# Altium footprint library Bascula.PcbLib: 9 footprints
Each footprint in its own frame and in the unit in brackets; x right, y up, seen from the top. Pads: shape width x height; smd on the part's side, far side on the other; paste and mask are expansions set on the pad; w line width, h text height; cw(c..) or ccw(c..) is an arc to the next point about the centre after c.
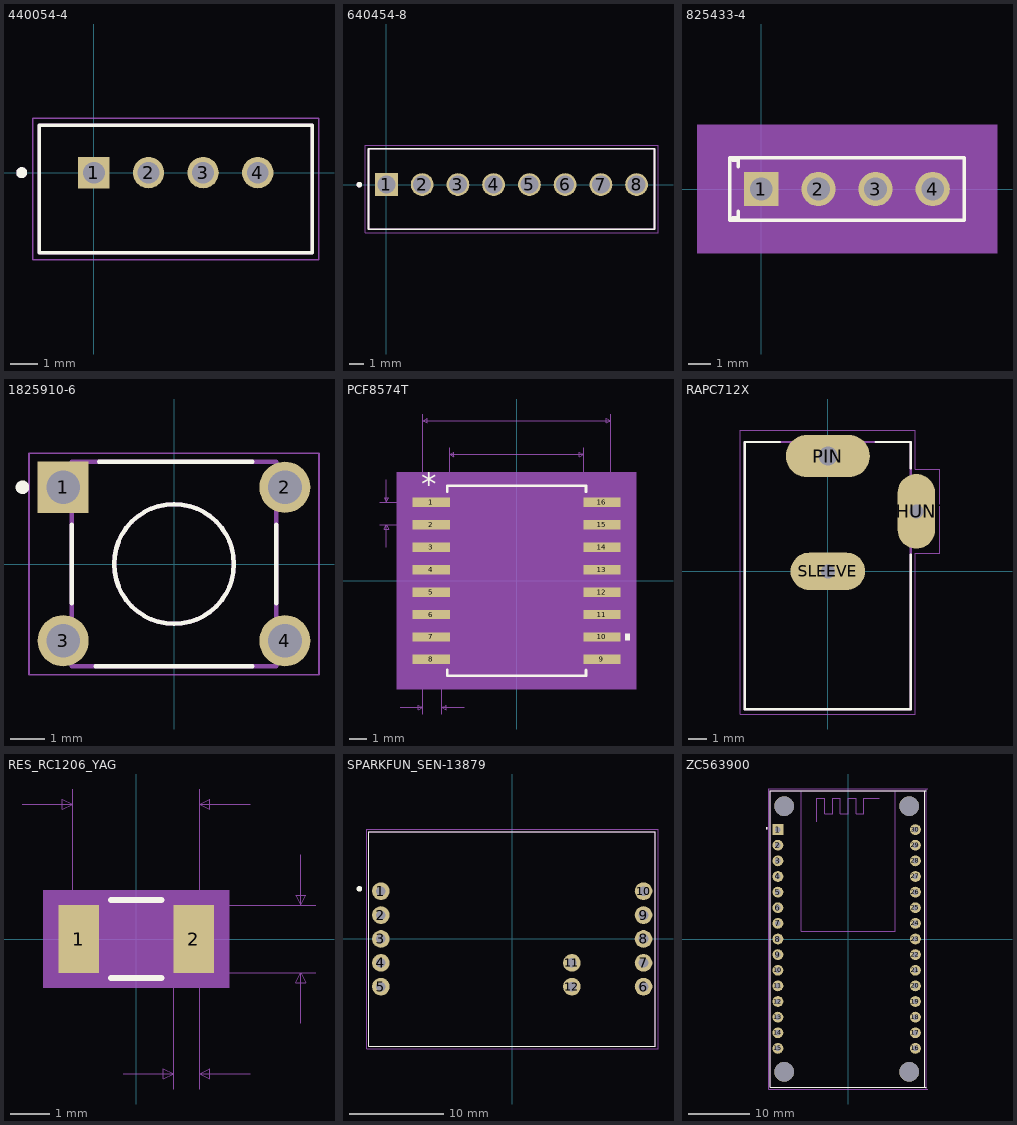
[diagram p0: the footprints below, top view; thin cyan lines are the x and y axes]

## 440054-4 [mm] "4 pin male connector for PCB"
pads (4):
  rect 1.15x1.15 hole 0.8: 1(0,0)
  round 1.15 hole 0.8: 2(2.007,0) 3(4.013,0) 4(6.02,0)
Top Overlay:
  circle w0.2: c-2.65,0 r0.1
  lines w0.127: -2,-2.95 8.02,-2.95 8.02,1.75 -2,1.75 -2,-2.95
Mechanical 13:
  circle w0.2: c-2.65,0 r0.1
  lines w0.127: -2,-2.95 8.02,-2.95 ; -2,-2.95 8.02,-2.95 ; -2,-2.95 -2,1.75 8.02,1.75 8.02,-2.95
Mechanical 15:
  lines w0.05: -2.25,-3.2 8.27,-3.2 8.27,2 -2.25,2 -2.25,-3.2
3D body "440054-4.stp": height 6.06, standoff -3.39, extent -1.977,-2.973 8.023,1.727

## 640454-8 [mm] "8 pin male header connector 2.54MM"
pads (8):
  rect 1.62x1.62 hole 1.27: 1(0,0)
  round 1.62 hole 1.27: 2(2.54,0) 3(5.08,0) 4(7.62,0) 5(10.16,0) 6(12.7,0) 7(15.24,0) 8(17.78,0)
Top Overlay:
  circle w0.2: c-1.92,0 r0.1
  lines w0.127: -1.27,-3.17 -1.27,2.55 19.05,2.55 19.05,-3.17 -1.27,-3.17
Mechanical 13:
  circle w0.2: c-1.92,0 r0.1
  lines w0.127: -1.27,-3.17 -1.27,2.55 19.05,2.55 19.05,-3.17 ; -1.27,-3.17 19.05,-3.17 ; -1.27,-3.17 19.05,-3.17
Mechanical 15:
  lines w0.05: -1.52,-3.42 -1.52,2.8 19.3,2.8 19.3,-3.42 -1.52,-3.42
3D body "640454-8.stp": height 10.09, standoff -3.5, extent -1.245,-3.129 19.075,2.591

## 825433-4 [mil] "HDR_1X4_0.100\""
pads (4):
  rect 60x60 hole 40 mask+0: 1(0,0)
  round 60 hole 40 mask+0: 2(100,0) 3(200,0) 4(300,0)
Top Overlay:
  lines w6: -50,-50 -40,-50 -40,-38.46 ; -50,50 -40,50 -40,38.46 ; -55,-55 355,-55 355,55 -55,55 -55,-55
Mechanical 5:
  region: 412.5,-112.5 -112.5,-112.5 -112.5,112.5 412.5,112.5
Mechanical 7:
  lines w1: 0,-110 0,-40 ; 50,-100 0,-100 ; 250,-100 300,-100 ; 300,-110 300,-40 ; 0,-100 10,-105 10,-95 0,-100 ; 300,-100 290,-105 290,-95 300,-100 ; 400,0 395,-10 405,-10 400,0 ; 400,0 395,10 405,10 400,0 ; 340,0 410,0 340,0
  text "Default Padstyle: OX60Y60D40P" at -212.5,-250 h50
  text "Pin 1 Padstyle: SX60Y60D40P" at -187.5,-350 h50
  text "Alt 1 Padstyle: OX60Y90D30P" at -187.5,-450 h50
  text "Alt 2 Padstyle: OX90Y60D30P" at -187.5,-550 h50
  text ".3in/7.62mm (4 @ .1in/3mm)" at -12.5,-125 h25
Mechanical 13:
  lines w1: -50,-50 -40,-50 -40,50 -50,50 ; -50,-50 350,-50 350,50 -50,50 ; -50,-50 -50,50
Mechanical 15:
  region: 360,60 -60,60 -60,-60 360,-60
  lines w6: -60,-60 -60,60 360,60 360,-60 -60,-60
3D body "825433-4.stp": height 374.52, standoff -125.48, extent -47,-94.7 353,49
3D body: height 10, standoff 0, extent 0,0 10,10

## 1825910-6 [mm] "NO Button"
pads (4):
  rect 1.498x1.498 hole 0.99: 1(-3.25,2.25)
  round 1.498 hole 0.99: 2(3.25,2.25) 3(-3.25,-2.25) 4(3.25,-2.25)
Top Overlay:
  circle w0.2: c-4.445,2.25 r0.1
  circle w0.127: c0,0 r1.755
  lines w0.127: -2.995,-1.15 -2.995,1.15 ; -2.3,-2.995 2.3,-2.995 ; -2.2,2.995 2.3,2.995 ; 3,-1.15 3,1.15
Mechanical 13:
  circle w0.127: c0,0 r1.755
  lines w0.127: -2.995,-2.995 2.995,-2.995 2.995,2.995 -2.995,2.995 -2.995,-2.995
Mechanical 15:
  lines w0.05: -4.25,-3.25 4.25,-3.25 4.25,3.25 -4.25,3.25 -4.25,-3.25
3D body "1825910-6.STEP": height 5.01, standoff -3.51, extent -3.847,-2.944 3.951,3.046

## PCF8574T [mil] "IC Expansor ES"
pads (16):
  rect 83x21 smd paste+0 mask+0: 1(-190,175) 2(-190,125) 3(-190,75) 4(-190,25) 5(-190,-25) 6(-190,-75) 7(-190,-125) 8(-190,-175) 9(190,-175) 10(190,-125) 11(190,-75) 12(190,-25) 13(190,25) 14(190,75) 15(190,125) 16(190,175)
Top Overlay:
  region: 241.5,-117.5 251.5,-117.5 251.5,-132.5 241.5,-132.5
  lines w6: -154.5,-198.6 -154.5,-211.5 154.5,-211.5 154.5,-198.6 ; -154.5,198.6 -154.5,211.5 154.5,211.5 154.5,198.6
  text "*" at -212.5,191 h50
Mechanical 5:
  region: 266.5,-241.5 -266.5,-241.5 -266.5,241.5 266.5,241.5
Mechanical 7:
  lines w1: -305,125 -190,125 ; -305,175 -190,175 ; -290,75 -290,125 ; -290,225 -290,175 ; -259.5,-281.5 -209.5,-281.5 ; -209.5,-296.5 -209.5,0 -209.5,371.5 ; -166.5,-296.5 -166.5,0 ; -149.5,0 -149.5,296.5 ; -116.5,-281.5 -166.5,-281.5 ; 0,-206.5 264.5,-206.5 ; 0,206.5 264.5,206.5 ; 149.5,0 149.5,296.5 ; 209.5,0 209.5,371.5 ; -290,125 -295,115 -285,115 -290,125 ; -290,175 -295,185 -285,185 -290,175 ; -209.5,-281.5 -219.5,-276.5 -219.5,-286.5 -209.5,-281.5 ; -209.5,356.5 209.5,356.5 ; -209.5,356.5 -199.5,361.5 -199.5,351.5 -209.5,356.5 ; -166.5,-281.5 -156.5,-276.5 -156.5,-286.5 -166.5,-281.5 ; -149.5,281.5 149.5,281.5 ; -149.5,281.5 -139.5,286.5 -139.5,276.5 -149.5,281.5 ; 149.5,281.5 139.5,286.5 139.5,276.5 149.5,281.5 ; 209.5,356.5 199.5,361.5 199.5,351.5 209.5,356.5 ; 249.5,-206.5 249.5,206.5 ; 249.5,-206.5 244.5,-196.5 254.5,-196.5 249.5,-206.5 ; 249.5,206.5 244.5,196.5 254.5,196.5 249.5,206.5
  text "Default Padstyle: RX83Y21D0T" at -350,-406.5 h50
  text "Pin One Padstyle: RX83Y21D0T" at -350,-466.5 h50
  text "Alt 1 Padstyle: OX60Y90D30P" at -337.5,-646.5 h50
  text "Alt 2 Padstyle: OX90Y60D30P" at -337.5,-706.5 h50
  text "0.299in/7.595mm" at -93.75,301.5 h25
  text "0.419in/10.643mm" at -100,376.5 h25
  text "0.413in/10.49mm" at 269.5,-12.5 h25
  text "0.05in/1.27mm" at -472.5,137.5 h25
  text "0.043in/1.092mm" at -281.75,-326.5 h25
Mechanical 13:
  lines w0: -12,206.5 ccw(c0,206.5) 12,206.5
  lines w1: -209.5,-184.5 -209.5,-165.5 -149.5,-165.5 -149.5,-184.5 -209.5,-184.5 ; -209.5,-134.5 -209.5,-115.5 -149.5,-115.5 -149.5,-134.5 -209.5,-134.5 ; -209.5,-84.5 -209.5,-65.5 -149.5,-65.5 -149.5,-84.5 -209.5,-84.5 ; -209.5,-34.5 -209.5,-15.5 -149.5,-15.5 -149.5,-34.5 -209.5,-34.5 ; -209.5,15.5 -209.5,34.5 -149.5,34.5 -149.5,15.5 -209.5,15.5 ; -209.5,65.5 -209.5,84.5 -149.5,84.5 -149.5,65.5 -209.5,65.5 ; -209.5,115.5 -209.5,134.5 -149.5,134.5 -149.5,115.5 -209.5,115.5 ; -209.5,165.5 -209.5,184.5 -149.5,184.5 -149.5,165.5 -209.5,165.5 ; -149.5,-206.5 149.5,-206.5 149.5,206.5 -149.5,206.5 -149.5,-206.5 ; 149.5,-184.5 149.5,-165.5 209.5,-165.5 209.5,-184.5 149.5,-184.5 ; 149.5,-134.5 149.5,-115.5 209.5,-115.5 209.5,-134.5 149.5,-134.5 ; 149.5,-84.5 149.5,-65.5 209.5,-65.5 209.5,-84.5 149.5,-84.5 ; 149.5,-34.5 149.5,-15.5 209.5,-15.5 209.5,-34.5 149.5,-34.5 ; 149.5,15.5 149.5,34.5 209.5,34.5 209.5,15.5 149.5,15.5 ; 149.5,65.5 149.5,84.5 209.5,84.5 209.5,65.5 149.5,65.5 ; 149.5,115.5 149.5,134.5 209.5,134.5 209.5,115.5 149.5,115.5 ; 149.5,165.5 149.5,184.5 209.5,184.5 209.5,165.5 149.5,165.5
  text "*" at -147,153.5 h50
Mechanical 15:
  region: -169.5,-205.5 -251.5,-205.5 -251.5,205.5 -169.5,205.5 -169.5,226.5 169.5,226.5 169.5,205.5 251.5,205.5 251.5,-205.5 169.5,-205.5 169.5,-226.5 -169.5,-226.5
  lines w6: -251.5,-205.5 -251.5,205.5 -169.5,205.5 -169.5,226.5 169.5,226.5 169.5,205.5 251.5,205.5 251.5,-205.5 169.5,-205.5 169.5,-226.5 -169.5,-226.5 -169.5,-205.5 -251.5,-205.5
3D body "SOT162-1_NXP.step": height 104.09, standoff 0, extent -208.98,-207 210,205.99
3D body: height 10, standoff 0, extent 0,0 10,10

## RAPC712X [mm] "Power Jack Barrel TH"
pads (3):
  oval 4.56x2.28 hole 1.02 square: PIN(0,6.25)
  oval 2.025x4.05 hole 0.76 square: SHUNT(4.8,3.25)
  oval 4.05x2.025 hole 0.76 square: SLEEVE(0,0)
Top Overlay:
  lines w0.127: -2.6,7.01 -4.5,7.01 -4.5,-7.49 4.5,-7.49 4.5,0.905 ; 2.6,7.01 4.5,7.01 4.5,5.595
Mechanical 13:
  lines w0.127: -4.5,-7.49 -4.5,7.01 4.5,7.01 4.5,-7.49 -4.5,-7.49
Mechanical 15:
  lines w0.05: -4.75,-7.74 -4.75,7.64 4.75,7.64 4.75,5.525 6.062,5.525 6.062,0.975 4.75,0.975 4.75,-7.74 -4.75,-7.74
3D body "RAPC712X.STEP": height 10.93, standoff -3.54, extent -4.496,-7.493 5.004,6.985

## RES_RC1206_YAG [mil] "1k SMD res 3216"
pads (2):
  rect 40x67 smd paste+0 mask+0: 1(-57,0) 2(57,0)
Top Overlay:
  lines w6: -24.89,-38.5 24.89,-38.5 ; -24.89,38.5 24.89,38.5
Mechanical 5:
  region: 92,-48.5 -92,-48.5 -92,48.5 92,48.5
Mechanical 7:
  lines w1: -113,133.5 -63,133.5 ; -63,0 -63,148.5 ; -13,-133.5 37,-133.5 ; 0,-33.5 178,-33.5 ; 0,33.5 178,33.5 ; 37,-148.5 37,0 ; 63,-148.5 63,0 63,148.5 ; 113,-133.5 63,-133.5 ; 113,133.5 63,133.5 ; 163,-83.5 163,-33.5 ; 163,83.5 163,33.5 ; -63,133.5 -73,128.5 -73,138.5 -63,133.5 ; 37,-133.5 27,-138.5 27,-128.5 37,-133.5 ; 63,-133.5 73,-138.5 73,-128.5 63,-133.5 ; 63,133.5 73,128.5 73,138.5 63,133.5 ; 163,-33.5 168,-43.5 158,-43.5 163,-33.5 ; 163,33.5 168,43.5 158,43.5 163,33.5
  text "0.026in/0.66mm" at -37.5,-178.5 h25
  text "0.126in/3.2mm" at -81.25,153.5 h25
  text "0.067in/1.702mm" at 183,-12.5 h25
  text "Alternate 2 Padstyle: OX90Y60D30P" at -412.5,-503.5 h50
  text "Alternate 1 Padstyle: OX60Y90D30P" at -412.5,-403.5 h50
  text "Default Padstyle: RX40Y67D0T" at -350,-303.5 h50
Mechanical 13:
  lines w1: -63,-33.5 -63,33.5 ; -63,-33.5 63,-33.5 ; -63,-33.5 -37,-33.5 -37,33.5 -63,33.5 ; -63,-33.5 -63,33.5 ; -63,33.5 63,33.5 ; 63,-33.5 63,33.5 ; 63,-33.5 63,33.5 ; 63,-33.5 37,-33.5 37,33.5 63,33.5
Mechanical 15:
  region: 87,-43.5 -87,-43.5 -87,43.5 87,43.5
  lines w6: -87,-43.5 87,-43.5 87,43.5 -87,43.5 -87,-43.5
3D body: height 10, standoff 0, extent 0,0 10,10
3D body "RES_RC1206_YAG.step": height 24.02, standoff 0, extent -60.99,-33.51 65,33.5

## SPARKFUN_SEN-13879 [mil]
pads (12):
  round 74 hole 40: 1(-550,200) 2(-550,100) 3(-550,0) 4(-550,-100) 5(-550,-200) 6(550,-200) 7(550,-100) 8(550,0) 9(550,100) 10(550,200) 11(250,-100) 12(250,-200)
Top Overlay:
  circle w11.81: c-640,210 r5.91
  lines w5: -600,-450 -600,450 600,450 600,-450 -600,-450
Mechanical 13:
  lines w5: -600,-450 600,-450 600,450 -600,450 -600,-450
Mechanical 15:
  lines w1.97: -609.84,-459.84 610.63,-459.84 610.63,459.45 -609.84,459.45 -609.84,-459.84
3D body "HX711.stp": height 280.03, standoff -235.72, extent -600,-450 600,450

## ZC563900 [mil] "NodeMCU ESP8266"
pads (34):
  rect 69x69 hole 35: 1(-450,700)
  round 69 hole 35: 2(-450,600) 3(-450,500) 4(-450,400) 5(-450,300) 6(-450,200) 7(-450,100) 8(-450,0) 9(-450,-100) 10(-450,-200) 11(-450,-300) 12(-450,-400) 13(-450,-500) 14(-450,-600) 15(-450,-700) 16(430,-700) 17(430,-600) 18(430,-500) 19(430,-400) 20(430,-300) 21(430,-200) 22(430,-100) 23(430,0) 24(430,100) 25(430,200) 26(430,300) 27(430,400) 28(430,500) 29(430,600) 30(430,700)
  round 125.98 hole 125.98 unplated: ""(-410,-850) ""(-410,850) ""(390,-850) ""(390,850)
Top Overlay:
  circle w7.87: c-521.65,708.66 r3.94
  lines w5: 490,-950 490,950 ; 500,-950 -500,-950 -500,950 500,950
Mechanical 13:
  circle w7.87: c-521.65,708.66 r3.94
  lines w5: -200,750 -200,900 -150,900 -150,800 -100,800 -100,900 -50,900 -50,800 0,800 0,900 50,900 50,800 100,800 100,900 200,900 ; 490,-950 490,950 ; 500,-950 -500,-950 -500,950 -300,950 ; 500,950 300,950 ; -300,950 -300,50 300,50 300,950 ; -300,950 300,950
Mechanical 15:
  lines w1.97: 499.84,-959.84 499.84,959.84 ; 509.84,-959.84 -509.84,-959.84 -509.84,959.84 509.84,959.84
3D body "ESP8266 v7.stp": height 305.23, standoff -249.5, extent -505.9,-966.02 500,956.02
